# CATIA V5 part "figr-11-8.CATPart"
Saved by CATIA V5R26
Part number: Part1
Bounding box of the stored display mesh (mm): x -50 to 50, y -39.834 to 41.856, z -25 to 25
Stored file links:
  D:\_Deepak\CATIA\CATIA V5-6R2016_Deepak\Resources\Part files\Partfiles\c11_catia_v5_6r2016_prt\figr-11-8.CATPart
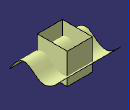
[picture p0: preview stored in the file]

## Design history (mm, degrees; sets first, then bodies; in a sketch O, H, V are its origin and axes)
Set1
  Sketch1 on yz-plane, origin (0, 0, 0), H (0, 1, 0), V (0, 0, 1)
    spline S1 through (-39.8338, -18.0686) (-4.7892, 0) (1.9431, -5.3632) (41.8556, 3.6938)
    point P1 (-4.7892, 0)
    coincidence: P1 H
  Extrude1: Element1 Sketch1, Lim1 50, Lim2 50, Direction yz-plane
  Sketch2 on xy-plane, origin (0, 0, 0), H (1, 0, 0), V (0, 1, 0)
    line L1 (-20.1634, 25.5896) -> (20.7534, 25.5896)
    line L2 (20.7534, 25.5896) -> (20.7534, -23.3463)
    line L3 (20.7534, -23.3463) -> (-20.1634, -23.3463)
    line L4 (-20.1634, -23.3463) -> (-20.1634, 25.5896)
    horizontal: L1 H, L3 H
    vertical: L2 V, L4 V
  Extrude2: Element1 Sketch2, Lim1 25, Lim2 25, Direction xy-plane
Body1 (main body)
